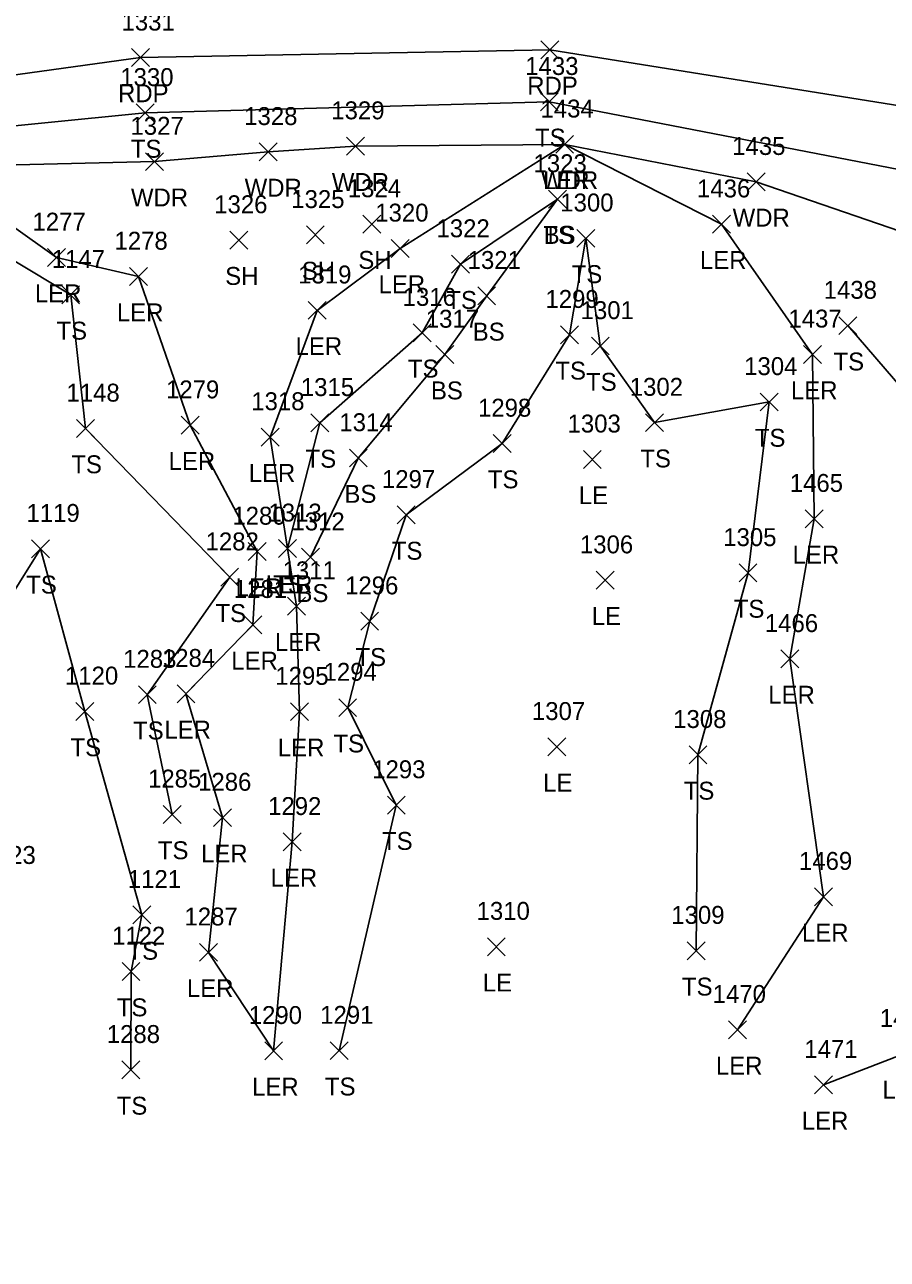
# Model space of a CAD drawing. Extents: x 1586965 to 1590952, y 716317 to 720029.
# Drawn here: x 1587710.9 to 1587807.3, y 719699 to 719836.9 of the extents above; entities that cross this region are included whole.
import ezdxf

# ---------------------------------------------------------------- set-up
doc = ezdxf.new("R2010")
doc.units = 0
for name, color, linetype in [('L_A', 7, 'Continuous'), ('L_I', 7, 'Continuous'), ('L_TIC', 7, 'Continuous'), ('LARO', 7, 'Continuous'), ('LAWA', 7, 'Continuous'), ('LELB', 7, 'Continuous'), ('P_A', 7, 'Continuous'), ('P_I', 7, 'Continuous'), ('P_TIC', 7, 'Continuous'), ('PET', 7, 'Continuous')]:
    doc.layers.add(name, color=color, linetype=linetype)

msp = doc.modelspace()

# ---------------------------------------------------------------- linework, layer by layer
at = {"layer": 'L_TIC'}
for points in [[(1587768.54, 719827.25), (1587770.54, 719829.25)], [(1587770.54, 719827.25), (1587768.54, 719829.25)], [(1587723.39, 719826.01), (1587725.39, 719828.01)], [(1587725.39, 719826.01), (1587723.39, 719828.01)], [(1587737.15, 719821.66), (1587739.15, 719823.66)], [(1587739.15, 719821.66), (1587737.15, 719823.66)], [(1587746.89, 719822.3), (1587748.89, 719824.3)], [(1587748.89, 719822.3), (1587746.89, 719824.3)], [(1587770.26, 719822.5), (1587772.26, 719824.5)], [(1587772.26, 719822.5), (1587770.26, 719824.5)], [(1587770.26, 719822.5), (1587772.26, 719824.5)], [(1587772.26, 719822.5), (1587770.26, 719824.5)], [(1587724.45, 719820.57), (1587726.45, 719822.57)], [(1587726.45, 719820.57), (1587724.45, 719822.57)], [(1587791.66, 719818.32), (1587793.66, 719820.32)], [(1587793.66, 719818.32), (1587791.66, 719820.32)], [(1587769.47, 719816.39), (1587771.47, 719818.39)], [(1587771.47, 719816.39), (1587769.47, 719818.39)], [(1587769.47, 719816.39), (1587771.47, 719818.39)], [(1587771.47, 719816.39), (1587769.47, 719818.39)], [(1587748.72, 719813.6), (1587750.72, 719815.6)], [(1587750.72, 719813.6), (1587748.72, 719815.6)], [(1587787.78, 719813.58), (1587789.78, 719815.58)], [(1587789.78, 719813.58), (1587787.78, 719815.58)], [(1587742.41, 719812.39), (1587744.41, 719814.39)], [(1587744.41, 719812.39), (1587742.41, 719814.39)], [(1587772.63, 719812.01), (1587774.63, 719814.01)], [(1587774.63, 719812.01), (1587772.63, 719814.01)], [(1587733.86, 719811.81), (1587735.86, 719813.81)], [(1587735.86, 719811.81), (1587733.86, 719813.81)], [(1587751.88, 719810.88), (1587753.88, 719812.88)], [(1587753.88, 719810.88), (1587751.88, 719812.88)], [(1587713.5, 719809.87), (1587715.5, 719811.87)], [(1587715.5, 719809.87), (1587713.5, 719811.87)], [(1587758.63, 719809.13), (1587760.63, 719811.13)], [(1587760.63, 719809.13), (1587758.63, 719811.13)], [(1587722.66, 719807.74), (1587724.66, 719809.74)], [(1587724.66, 719807.74), (1587722.66, 719809.74)], [(1587715.08, 719805.7), (1587717.08, 719807.7)], [(1587717.08, 719805.7), (1587715.08, 719807.7)], [(1587761.55, 719805.59), (1587763.55, 719807.59)], [(1587763.55, 719805.59), (1587761.55, 719807.59)], [(1587742.62, 719803.97), (1587744.62, 719805.97)], [(1587744.62, 719803.97), (1587742.62, 719805.97)], [(1587801.88, 719802.26), (1587803.88, 719804.26)], [(1587803.88, 719802.26), (1587801.88, 719804.26)], [(1587754.34, 719801.47), (1587756.34, 719803.47)], [(1587756.34, 719801.47), (1587754.34, 719803.47)], [(1587770.81, 719801.24), (1587772.81, 719803.24)], [(1587772.81, 719801.24), (1587770.81, 719803.24)], [(1587774.24, 719799.99), (1587776.24, 719801.99)], [(1587776.24, 719799.99), (1587774.24, 719801.99)], [(1587756.88, 719799.03), (1587758.88, 719801.03)], [(1587758.88, 719799.03), (1587756.88, 719801.03)], [(1587797.95, 719799.05), (1587799.95, 719801.05)], [(1587799.95, 719799.05), (1587797.95, 719801.05)], [(1587793.09, 719793.74), (1587795.09, 719795.74)], [(1587795.09, 719793.74), (1587793.09, 719795.74)], [(1587742.91, 719791.4), (1587744.91, 719793.4)], [(1587744.91, 719791.4), (1587742.91, 719793.4)], [(1587780.3, 719791.43), (1587782.3, 719793.43)], [(1587782.3, 719791.43), (1587780.3, 719793.43)], [(1587716.74, 719790.78), (1587718.74, 719792.78)], [(1587718.74, 719790.78), (1587716.74, 719792.78)], [(1587728.43, 719791.14), (1587730.43, 719793.14)], [(1587730.43, 719791.14), (1587728.43, 719793.14)], [(1587737.37, 719789.82), (1587739.37, 719791.82)], [(1587739.37, 719789.82), (1587737.37, 719791.82)], [(1587763.27, 719789.1), (1587765.27, 719791.1)], [(1587765.27, 719789.1), (1587763.27, 719791.1)], [(1587747.21, 719787.48), (1587749.21, 719789.48)], [(1587749.21, 719787.48), (1587747.21, 719789.48)], [(1587773.35, 719787.33), (1587775.35, 719789.33)], [(1587775.35, 719787.33), (1587773.35, 719789.33)], [(1587752.55, 719781.13), (1587754.55, 719783.13)], [(1587754.55, 719781.13), (1587752.55, 719783.13)], [(1587798.14, 719780.7), (1587800.14, 719782.7)], [(1587800.14, 719780.7), (1587798.14, 719782.7)], [(1587711.7, 719777.35), (1587713.7, 719779.35)], [(1587713.7, 719777.35), (1587711.7, 719779.35)], [(1587735.92, 719777.04), (1587737.92, 719779.04)], [(1587737.92, 719777.04), (1587735.92, 719779.04)], [(1587739.3, 719777.39), (1587741.3, 719779.39)], [(1587741.3, 719777.39), (1587739.3, 719779.39)], [(1587739.3, 719777.39), (1587741.3, 719779.39)], [(1587741.3, 719777.39), (1587739.3, 719779.39)], [(1587741.86, 719776.4), (1587743.86, 719778.4)], [(1587743.86, 719776.4), (1587741.86, 719778.4)], [(1587790.74, 719774.65), (1587792.74, 719776.65)], [(1587792.74, 719774.65), (1587790.74, 719776.65)], [(1587732.84, 719774.17), (1587734.84, 719776.17)], [(1587734.84, 719774.17), (1587732.84, 719776.17)], [(1587774.79, 719773.84), (1587776.79, 719775.84)], [(1587776.79, 719773.84), (1587774.79, 719775.84)], [(1587740.31, 719770.94), (1587742.31, 719772.94)], [(1587742.31, 719770.94), (1587740.31, 719772.94)], [(1587748.48, 719769.26), (1587750.48, 719771.26)], [(1587750.48, 719769.26), (1587748.48, 719771.26)], [(1587735.44, 719768.86), (1587737.44, 719770.86)], [(1587737.44, 719768.86), (1587735.44, 719770.86)], [(1587795.42, 719765.05), (1587797.42, 719767.05)], [(1587797.42, 719765.05), (1587795.42, 719767.05)], [(1587723.64, 719761.06), (1587725.64, 719763.06)], [(1587725.64, 719761.06), (1587723.64, 719763.06)], [(1587727.96, 719761.16), (1587729.96, 719763.16)], [(1587729.96, 719761.16), (1587727.96, 719763.16)], [(1587746.02, 719759.61), (1587748.02, 719761.61)], [(1587748.02, 719759.61), (1587746.02, 719761.61)], [(1587716.65, 719759.19), (1587718.65, 719761.19)], [(1587718.65, 719759.19), (1587716.65, 719761.19)], [(1587740.63, 719759.16), (1587742.63, 719761.16)], [(1587742.63, 719759.16), (1587740.63, 719761.16)], [(1587769.37, 719755.23), (1587771.37, 719757.23)], [(1587771.37, 719755.23), (1587769.37, 719757.23)], [(1587785.15, 719754.34), (1587787.15, 719756.34)], [(1587787.15, 719754.34), (1587785.15, 719756.34)], [(1587751.45, 719748.73), (1587753.45, 719750.73)], [(1587753.45, 719748.73), (1587751.45, 719750.73)], [(1587726.41, 719747.69), (1587728.41, 719749.69)], [(1587728.41, 719747.69), (1587726.41, 719749.69)], [(1587732.05, 719747.33), (1587734.05, 719749.33)], [(1587734.05, 719747.33), (1587732.05, 719749.33)], [(1587739.82, 719744.62), (1587741.82, 719746.62)], [(1587741.82, 719744.62), (1587739.82, 719746.62)], [(1587799.18, 719738.5), (1587801.18, 719740.5)], [(1587801.18, 719738.5), (1587799.18, 719740.5)], [(1587723.02, 719736.47), (1587725.02, 719738.47)], [(1587725.02, 719736.47), (1587723.02, 719738.47)], [(1587730.48, 719732.29), (1587732.48, 719734.29)], [(1587732.48, 719732.29), (1587730.48, 719734.29)], [(1587762.63, 719732.92), (1587764.63, 719734.92)], [(1587764.63, 719732.92), (1587762.63, 719734.92)], [(1587784.95, 719732.47), (1587786.95, 719734.47)], [(1587786.95, 719732.47), (1587784.95, 719734.47)], [(1587721.82, 719730.15), (1587723.82, 719732.15)], [(1587723.82, 719730.15), (1587721.82, 719732.15)], [(1587789.57, 719723.64), (1587791.57, 719725.64)], [(1587791.57, 719723.64), (1587789.57, 719725.64)], [(1587737.75, 719721.29), (1587739.75, 719723.29)], [(1587739.75, 719721.29), (1587737.75, 719723.29)], [(1587745.07, 719721.31), (1587747.07, 719723.31)], [(1587747.07, 719721.31), (1587745.07, 719723.31)], [(1587721.81, 719719.17), (1587723.81, 719721.17)], [(1587723.81, 719719.17), (1587721.81, 719721.17)], [(1587799.16, 719717.5), (1587801.16, 719719.5)], [(1587801.16, 719717.5), (1587799.16, 719719.5)]]:
    msp.add_lwpolyline(points, dxfattribs=at)
at = {"layer": 'LARO'}
for points in [[(1587704.58, 719817.92), (1587714.5, 719810.87), (1587723.66, 719808.74), (1587729.43, 719792.14), (1587736.92, 719778.04), (1587736.44, 719769.86), (1587728.96, 719762.16), (1587733.05, 719748.33), (1587731.48, 719733.29), (1587738.75, 719722.29), (1587740.82, 719745.62), (1587741.63, 719760.16), (1587741.31, 719771.94), (1587740.3, 719778.39), (1587738.37, 719790.82), (1587743.62, 719804.97), (1587752.88, 719811.88), (1587771.26, 719823.5), (1587788.78, 719814.58), (1587798.95, 719800.05), (1587799.14, 719781.7), (1587796.42, 719766.05), (1587800.18, 719739.5), (1587790.57, 719724.64)], [(1587800.16, 719718.5), (1587809.15, 719721.97), (1587823.11, 719714.7), (1587837.15, 719708.08), (1587843.73, 719719.21), (1587855.51, 719722.88), (1587868.54, 719717.9), (1587875.84, 719711.92), (1587887.2, 719718.64), (1587899.12, 719726.92), (1587909.6, 719739.77), (1587919.76, 719737.52), (1587914.82, 719726.74), (1587909.45, 719708.39), (1587904.27, 719696.49)]]:
    msp.add_lwpolyline(points, dxfattribs=at)
at = {"layer": 'LAWA'}
msp.add_lwpolyline([(1587401.27, 719626.51), (1587435.01, 719634.6), (1587448.14, 719647.08), (1587470.91, 719665.01), (1587461.04, 719696.06), (1587450.54, 719719.33), (1587487.07, 719738.78), (1587518.72, 719752.12), (1587550.39, 719765.58), (1587600.64, 719780.12), (1587625.51, 719792.71), (1587653.44, 719805), (1587664.38, 719814.47), (1587690.31, 719819.83), (1587699.11, 719820.97), (1587725.45, 719821.57), (1587738.15, 719822.66), (1587747.89, 719823.3), (1587771.26, 719823.5), (1587792.66, 719819.32), (1587813.67, 719812.11)], dxfattribs=at)
at = {"layer": 'LELB'}
for points in [[(1587398.24, 719722.21), (1587438.94, 719742.74), (1587477.78, 719760.7), (1587507.65, 719771.73), (1587544.05, 719780.86), (1587591.35, 719799.64), (1587619.1, 719805.45), (1587663.03, 719817.76), (1587689.98, 719823.61), (1587724.39, 719827.01), (1587769.54, 719828.25), (1587817.81, 719818.92)], [(1587398.24, 719722.21), (1587438.94, 719742.74), (1587477.78, 719760.7), (1587507.65, 719771.73), (1587544.05, 719780.86), (1587591.35, 719799.64), (1587619.1, 719805.45), (1587663.03, 719817.76), (1587689.98, 719823.61), (1587724.39, 719827.01), (1587769.54, 719828.25), (1587817.81, 719818.92)], [(1587740.3, 719778.39), (1587743.91, 719792.4), (1587755.34, 719802.47), (1587759.63, 719810.13), (1587770.47, 719817.39)], [(1587740.3, 719778.39), (1587743.91, 719792.4), (1587755.34, 719802.47), (1587759.63, 719810.13), (1587770.47, 719817.39)], [(1587742.86, 719777.4), (1587748.21, 719788.48), (1587757.88, 719800.03), (1587762.55, 719806.59), (1587770.47, 719817.39)], [(1587742.86, 719777.4), (1587748.21, 719788.48), (1587757.88, 719800.03), (1587762.55, 719806.59), (1587770.47, 719817.39)], [(1587651.83, 719700.97), (1587648.01, 719733.7), (1587631.26, 719740.62), (1587615.07, 719741.57), (1587623.3, 719748.63), (1587638.24, 719757.75), (1587639.59, 719745.07), (1587645.2, 719756.74), (1587652.38, 719771.7), (1587661.64, 719782.87), (1587675.63, 719789.54), (1587687.83, 719800.98), (1587693.68, 719811.37), (1587702.61, 719814.76), (1587716.08, 719806.7), (1587717.74, 719791.78), (1587733.84, 719775.17), (1587724.64, 719762.06), (1587727.41, 719748.69)], [(1587651.83, 719700.97), (1587648.01, 719733.7), (1587631.26, 719740.62), (1587615.07, 719741.57), (1587623.3, 719748.63), (1587638.24, 719757.75), (1587639.59, 719745.07), (1587645.2, 719756.74), (1587652.38, 719771.7), (1587661.64, 719782.87), (1587675.63, 719789.54), (1587687.83, 719800.98), (1587693.68, 719811.37), (1587702.61, 719814.76), (1587716.08, 719806.7), (1587717.74, 719791.78), (1587733.84, 719775.17), (1587724.64, 719762.06), (1587727.41, 719748.69)], [(1587746.07, 719722.31), (1587752.45, 719749.73), (1587747.02, 719760.61), (1587749.48, 719770.26), (1587753.55, 719782.13), (1587764.27, 719790.1), (1587771.81, 719802.24), (1587773.63, 719813.01), (1587775.24, 719800.99), (1587781.3, 719792.43), (1587794.09, 719794.74), (1587791.74, 719775.65), (1587786.15, 719755.34), (1587785.95, 719733.47)], [(1587746.07, 719722.31), (1587752.45, 719749.73), (1587747.02, 719760.61), (1587749.48, 719770.26), (1587753.55, 719782.13), (1587764.27, 719790.1), (1587771.81, 719802.24), (1587773.63, 719813.01), (1587775.24, 719800.99), (1587781.3, 719792.43), (1587794.09, 719794.74), (1587791.74, 719775.65), (1587786.15, 719755.34), (1587785.95, 719733.47)], [(1587802.88, 719803.26), (1587815.4, 719788.75), (1587834.3, 719779.97), (1587852.41, 719779.52), (1587871.55, 719786.46), (1587869.44, 719773.9), (1587860.31, 719756), (1587869.45, 719746.35), (1587885.49, 719756.11), (1587892.39, 719742.57)], [(1587802.88, 719803.26), (1587815.4, 719788.75), (1587834.3, 719779.97), (1587852.41, 719779.52), (1587871.55, 719786.46), (1587869.44, 719773.9), (1587860.31, 719756), (1587869.45, 719746.35), (1587885.49, 719756.11), (1587892.39, 719742.57)], [(1587683.35, 719718.25), (1587672.99, 719740.42), (1587671.28, 719750.8), (1587670.68, 719763.15), (1587682.17, 719777.24), (1587692.31, 719784.92), (1587698.7, 719772.55), (1587705.64, 719767.05), (1587712.7, 719778.35), (1587717.65, 719760.19), (1587724.02, 719737.47), (1587722.82, 719731.15), (1587722.81, 719720.17)], [(1587683.35, 719718.25), (1587672.99, 719740.42), (1587671.28, 719750.8), (1587670.68, 719763.15), (1587682.17, 719777.24), (1587692.31, 719784.92), (1587698.7, 719772.55), (1587705.64, 719767.05), (1587712.7, 719778.35), (1587717.65, 719760.19), (1587724.02, 719737.47), (1587722.82, 719731.15), (1587722.81, 719720.17)]]:
    msp.add_lwpolyline(points, dxfattribs=at)
at = {"layer": 'P_TIC'}
for points in [[(1587768.59, 719833.05), (1587770.59, 719835.05)], [(1587770.59, 719833.05), (1587768.59, 719835.05)], [(1587722.88, 719832.21), (1587724.88, 719834.21)], [(1587724.88, 719832.21), (1587722.88, 719834.21)]]:
    msp.add_lwpolyline(points, dxfattribs=at)
at = {"layer": 'PET'}
msp.add_lwpolyline([(1587395.82, 719726.18), (1587435.88, 719747.89), (1587475.69, 719765.52), (1587505.58, 719777), (1587541.23, 719789.76), (1587588.97, 719805.25), (1587616.65, 719812.47), (1587661.21, 719823.51), (1587689.19, 719828.4), (1587723.88, 719833.21), (1587769.59, 719834.05), (1587819.16, 719826.14)], dxfattribs=at)

# ---------------------------------------------------------------- texts
at = {"layer": 'L_A'}
for s, p in [('TS', (1587767.95, 719823.25)), ('TS', (1587722.8, 719822.01)), ('WDR', (1587735.51, 719817.66)), ('WDR', (1587745.25, 719818.3)), ('WDR', (1587768.62, 719818.5)), ('LER', (1587768.84, 719818.5)), ('WDR', (1587722.81, 719816.57)), ('WDR', (1587790.02, 719814.32)), ('TS', (1587768.88, 719812.39)), ('BS', (1587768.91, 719812.39)), ('SH', (1587748.21, 719809.6)), ('LER', (1587786.37, 719809.58)), ('SH', (1587733.34, 719807.81)), ('SH', (1587741.9, 719808.39)), ('TS', (1587772.04, 719808.01)), ('LER', (1587750.47, 719806.88)), ('LER', (1587712.08, 719805.87)), ('TS', (1587758.04, 719805.13)), ('LER', (1587721.24, 719803.74)), ('TS', (1587714.49, 719801.7)), ('BS', (1587760.99, 719801.59)), ('LER', (1587741.2, 719799.97)), ('TS', (1587801.29, 719798.26)), ('TS', (1587753.75, 719797.47)), ('TS', (1587770.22, 719797.24)), ('TS', (1587773.65, 719795.99)), ('BS', (1587756.32, 719795.03)), ('LER', (1587796.53, 719795.05)), ('TS', (1587792.5, 719789.74)), ('LER', (1587727.02, 719787.14)), ('TS', (1587742.32, 719787.4)), ('TS', (1587779.71, 719787.43)), ('TS', (1587716.15, 719786.78)), ('LER', (1587735.96, 719785.82)), ('TS', (1587762.68, 719785.1)), ('BS', (1587746.66, 719783.48)), ('LE', (1587772.84, 719783.33)), ('TS', (1587751.95, 719777.13)), ('LER', (1587796.72, 719776.7)), ('TS', (1587711.11, 719773.35)), ('LER', (1587737.88, 719773.39)), ('TS', (1587738.71, 719773.39)), ('LER', (1587734.5, 719773.04)), ('BS', (1587741.3, 719772.4)), ('TS', (1587790.15, 719770.65)), ('TS', (1587732.25, 719770.17)), ('LE', (1587774.28, 719769.84)), ('LER', (1587738.89, 719766.94)), ('TS', (1587747.89, 719765.26)), ('LER', (1587734.02, 719764.86)), ('LER', (1587794, 719761.05)), ('TS', (1587723.05, 719757.06)), ('LER', (1587726.54, 719757.16)), ('TS', (1587745.43, 719755.61)), ('TS', (1587716.06, 719755.19)), ('LER', (1587739.22, 719755.16)), ('LE', (1587768.86, 719751.23)), ('TS', (1587784.56, 719750.34)), ('TS', (1587750.86, 719744.73)), ('TS', (1587725.82, 719743.69)), ('LER', (1587730.64, 719743.33)), ('LER', (1587738.41, 719740.62)), ('LER', (1587797.76, 719734.5)), ('TS', (1587722.43, 719732.47)), ('LER', (1587729.06, 719728.29)), ('LE', (1587762.12, 719728.92)), ('TS', (1587784.36, 719728.47)), ('TS', (1587721.23, 719726.15)), ('LER', (1587788.15, 719719.64)), ('LER', (1587736.34, 719717.29)), ('TS', (1587744.48, 719717.31)), ('LER', (1587806.74, 719716.97)), ('TS', (1587721.22, 719715.17)), ('LER', (1587797.74, 719713.5))]:
    msp.add_text(s, height=2, dxfattribs=at).set_placement(p)
at = {"layer": 'L_I'}
for s, p in [('1433', (1587766.85, 719831.25)), ('1330', (1587721.62, 719830.01)), ('1328', (1587735.46, 719825.66)), ('1329', (1587745.19, 719826.3)), ('1434', (1587768.56, 719826.5)), ('1434', (1587768.56, 719826.5)), ('1327', (1587722.76, 719824.57)), ('1435', (1587789.97, 719822.32)), ('1323', (1587767.78, 719820.39)), ('1323', (1587767.78, 719820.39)), ('1324', (1587747.03, 719817.6)), ('1436', (1587786.04, 719817.58)), ('1325', (1587740.72, 719816.39)), ('1300', (1587770.77, 719816.01)), ('1326', (1587732.11, 719815.81)), ('1320', (1587750.1, 719814.88)), ('1277', (1587711.81, 719813.87)), ('1322', (1587756.94, 719813.13)), ('1278', (1587720.97, 719811.74)), ('1147', (1587713.96, 719809.7)), ('1321', (1587760.42, 719809.59)), ('1319', (1587741.49, 719807.97)), ('1316', (1587753.16, 719805.47)), ('1299', (1587769.11, 719805.24)), ('1438', (1587800.19, 719806.26)), ('1301', (1587773.04, 719803.99)), ('1317', (1587755.75, 719803.03)), ('1437', (1587796.25, 719803.05)), ('1304', (1587791.31, 719797.74)), ('1315', (1587741.79, 719795.4)), ('1302', (1587778.53, 719795.43)), ('1148', (1587715.61, 719794.78)), ('1279', (1587726.73, 719795.14)), ('1318', (1587736.25, 719793.82)), ('1298', (1587761.58, 719793.1)), ('1314', (1587746.09, 719791.48)), ('1303', (1587771.58, 719791.33)), ('1297', (1587750.85, 719785.13)), ('1465', (1587796.4, 719784.7)), ('1119', (1587711.14, 719781.35)), ('1280', (1587734.14, 719781.04)), ('1313', (1587738.17, 719781.39)), ('1313', (1587738.17, 719781.39)), ('1312', (1587740.74, 719780.4)), ('1282', (1587731.15, 719778.17)), ('1306', (1587772.96, 719777.84)), ('1305', (1587788.97, 719778.65)), ('1311', (1587739.75, 719774.94)), ('1296', (1587746.73, 719773.26)), ('1281', (1587734.31, 719772.86)), ('1466', (1587793.62, 719769.05)), ('1283', (1587721.94, 719765.06)), ('1284', (1587726.27, 719765.16)), ('1294', (1587744.33, 719763.61)), ('1120', (1587715.44, 719763.19)), ('1295', (1587738.94, 719763.16)), ('1307', (1587767.6, 719759.23)), ('1308', (1587783.38, 719758.34)), ('1293', (1587749.76, 719752.73)), ('1285', (1587724.72, 719751.69)), ('1286', (1587730.31, 719751.33)), ('1292', (1587738.13, 719748.62)), ('1123', (1587706.23, 719743.16)), ('1469', (1587797.43, 719742.5)), ('1121', (1587722.46, 719740.47)), ('1287', (1587728.79, 719736.29)), ('1310', (1587761.42, 719736.92)), ('1309', (1587783.17, 719736.47)), ('1122', (1587720.7, 719734.15)), ('1470', (1587787.79, 719727.64)), ('1290', (1587735.97, 719725.29)), ('1291', (1587743.95, 719725.31)), ('1472', (1587806.46, 719724.97)), ('1288', (1587720.11, 719723.17)), ('1471', (1587798.03, 719721.5))]:
    msp.add_text(s, height=2, dxfattribs=at).set_placement(p)
at = {"layer": 'P_A'}
for p in [(1587767.08, 719829.05), (1587721.37, 719828.21)]:
    msp.add_text('RDP', height=2, dxfattribs=at).set_placement(p)
at = {"layer": 'P_I'}
msp.add_text('1331', height=2, dxfattribs=at).set_placement((1587721.76, 719836.21))

doc.saveas('drawing.dxf')
